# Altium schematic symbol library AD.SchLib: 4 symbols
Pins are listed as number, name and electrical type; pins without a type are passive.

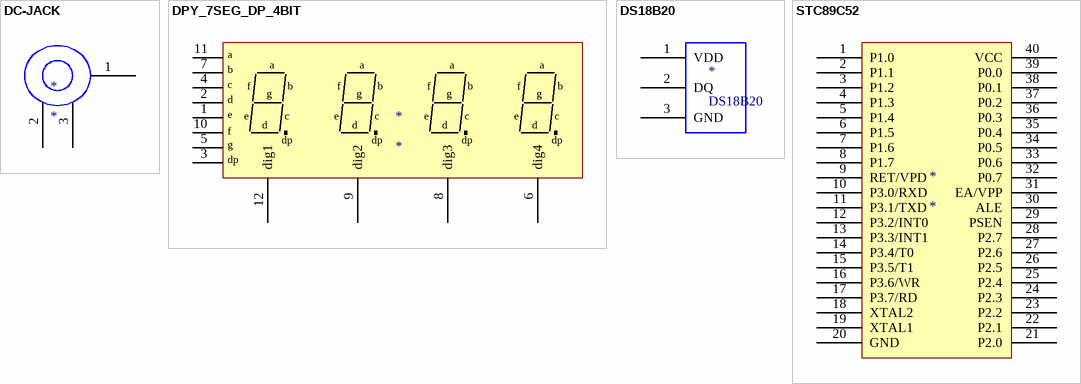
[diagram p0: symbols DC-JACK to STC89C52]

## DC-JACK
designator *
pins: 1, 2, 3

## DPY_7SEG_DP_4BIT
designator *
pins: 1 e, 2 d, 3 dp, 4 c, 5 g, 6 dig4, 7 b, 8 dig3, 9 dig2, 10 f, 11 a, 12 dig1

## DS18B20
designator *
footprint TO-92 (TO, Flat Index; 3 In-Line, Axial Leads; Body Dia. 4.6mm; Leads 0.41 x 0.39 mm (max))
pins: 1 VDD, 2 DQ, 3 GND

## STC89C52
designator *
pins: 1 P1.0, 2 P1.1, 3 P1.2, 4 P1.3, 5 P1.4, 6 P1.5, 7 P1.6, 8 P1.7, 9 RET/VPD, 10 P3.0/RXD, 11 P3.1/TXD, 12 P3.2/INT0, 13 P3.3/INT1, 14 P3.4/T0, 15 P3.5/T1, 16 P3.6/WR, 17 P3.7/RD, 18 XTAL2, 19 XTAL1, 20 GND, 21 P2.0, 22 P2.1, 23 P2.2, 24 P2.3, 25 P2.4, 26 P2.5, 27 P2.6, 28 P2.7, 29 PSEN, 30 ALE, 31 EA/VPP, 32 P0.7, 33 P0.6, 34 P0.5, 35 P0.4, 36 P0.3, 37 P0.2, 38 P0.1, 39 P0.0, 40 VCC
